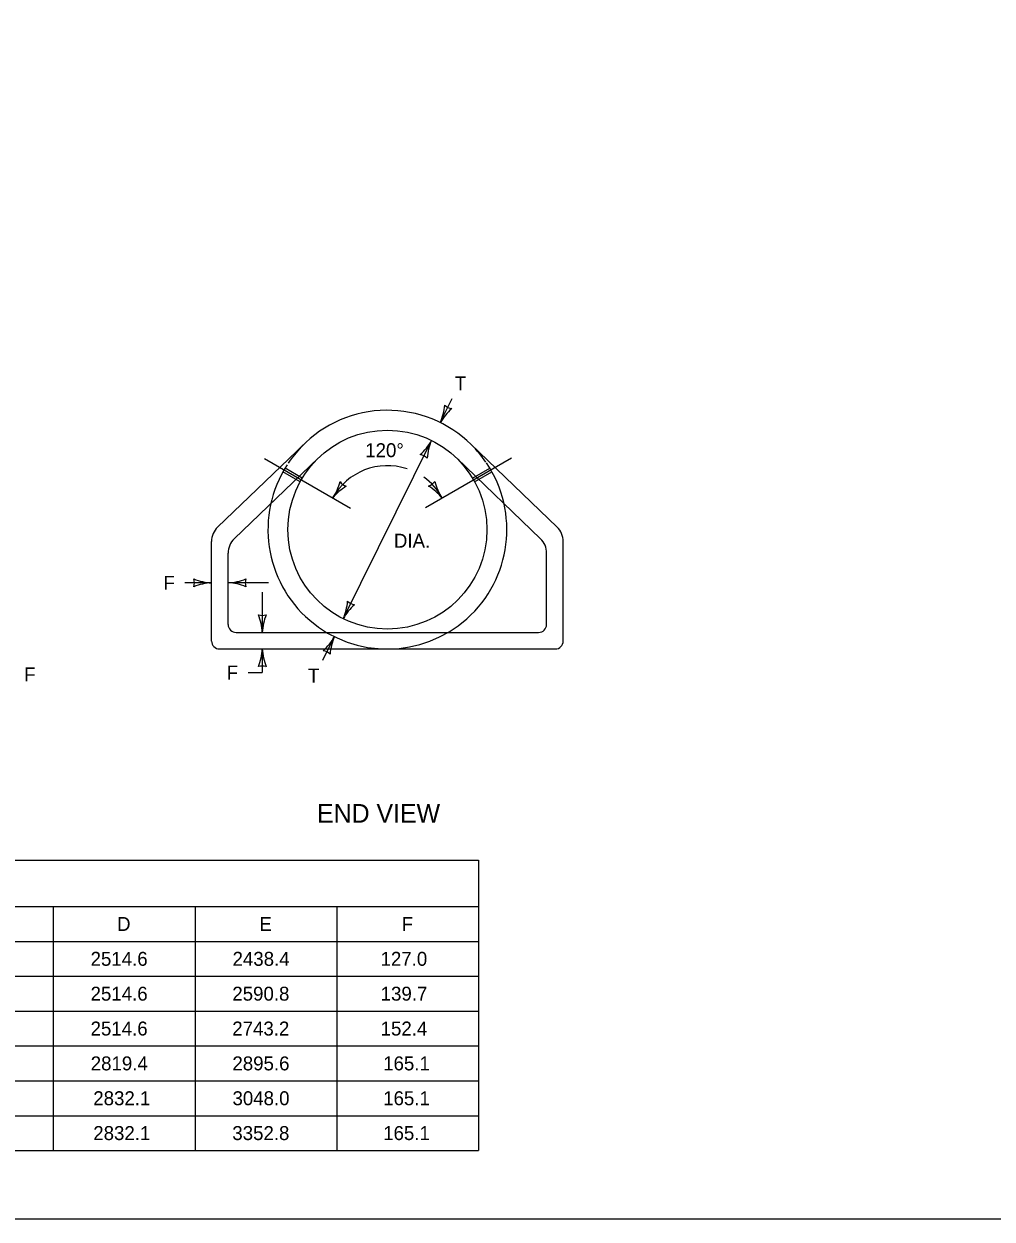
# Model space of a CAD drawing. Extents: x 49991.4 to 50022.1, y 49985 to 50011.4.
# Drawn here: x 50004.5 to 50008.67, y 49987.8 to 49992.94 of the extents above; entities that cross this region are included whole.
import ezdxf

# ---------------------------------------------------------------- set-up
doc = ezdxf.new("R2010")
doc.units = 0
for name, color, linetype in [('Level 1', 7, 'Continuous'), ('Level 2', 7, 'Continuous'), ('Level 3', 7, 'Continuous'), ('Level 4', 7, 'Continuous'), ('Level 5', 7, 'Continuous')]:
    doc.layers.add(name, color=color, linetype=linetype)

msp = doc.modelspace()

# ---------------------------------------------------------------- linework, layer by layer
at = {"layer": 'Level 1'}
for p, q in [((50005.7097, 49991.1365), (50005.3354, 49990.7771)), ((50006.4229, 49991.1349), (50006.7955, 49990.7771)), ((50005.769, 49991.0748), (50005.4069, 49990.727)), ((50006.3637, 49991.0731), (50006.724, 49990.727)), ((50005.3091, 49990.2865), (50005.3091, 49990.7154)), ((50006.8218, 49990.2865), (50006.8218, 49990.7154)), ((50005.3805, 49990.3579), (50005.3805, 49990.6653)), ((50006.7504, 49990.3579), (50006.7504, 49990.6653)), ((50005.4148, 49990.3237), (50006.7161, 49990.3237)), ((50005.3434, 49990.2523), (50006.7875, 49990.2523))]:
    msp.add_line(p, q, dxfattribs=at)
msp.add_lwpolyline([(49999.3835, 49998.9992), (50016.7501, 49998.9992), (50016.7501, 49987.7988), (49999.3835, 49987.7988)], close=True, dxfattribs=at)
msp.add_circle((50006.0655, 49990.766), 0.4281, dxfattribs=at)
for centre, radius, start, end in [((50006.0655, 49990.766), 0.5137, 45.3824, 135.9308), ((50005.3947, 49990.7154), 0.0856, 133.8358, 180), ((50006.7362, 49990.7154), 0.0856, 0, 46.1636), ((50005.4661, 49990.6653), 0.0856, 133.8272, 180), ((50006.6648, 49990.6653), 0.0856, 0, 46.1643), ((50005.4148, 49990.3579), 0.0342, 180, 270), ((50006.7161, 49990.3579), 0.0342, 270, 0), ((50005.3434, 49990.2865), 0.0342, 180, 270), ((50006.7875, 49990.2865), 0.0342, 270, 0)]:
    msp.add_arc(centre, radius, start, end, dxfattribs=at)
at = {"layer": 'Level 2'}
for p, q in [((50000.968, 49989.3439), (50006.458, 49989.3439)), ((50006.458, 49989.3439), (50006.458, 49988.0939)), ((50000.968, 49989.1439), (50006.458, 49989.1439)), ((50004.628, 49989.1439), (50004.628, 49988.0939)), ((50005.238, 49989.1439), (50005.238, 49988.0939)), ((50005.848, 49989.1439), (50005.848, 49988.0939)), ((50000.968, 49988.9939), (50006.458, 49988.9939)), ((50000.968, 49988.8439), (50006.458, 49988.8439)), ((50000.968, 49988.6939), (50006.458, 49988.6939)), ((50000.968, 49988.5439), (50006.458, 49988.5439)), ((50000.968, 49988.3939), (50006.458, 49988.3939)), ((50000.968, 49988.2439), (50006.458, 49988.2439)), ((50000.968, 49988.0939), (50006.458, 49988.0939))]:
    msp.add_line(p, q, dxfattribs=at)
at = {"layer": 'Level 3'}
for p, q in [((50006.2932, 49991.2264), (50006.3444, 49991.33)), ((50005.8756, 49990.3823), (50006.2552, 49991.1497)), ((50005.3091, 49990.5371), (50005.1948, 49990.5371)), ((50005.5539, 49990.5371), (50005.3805, 49990.5371)), ((50005.5275, 49990.4971), (50005.5275, 49990.3237)), ((50005.7874, 49990.2039), (50005.8377, 49990.3055)), ((50005.5275, 49990.2523), (50005.5275, 49990.1509)), ((50005.4668, 49990.1509), (50005.5275, 49990.1509))]:
    msp.add_line(p, q, dxfattribs=at)
for centre, radius, start, end in [((50006.0795, 49991.3192), 0.233, 336.5283, 355.7782), ((50006.4883, 49991.1198), 0.2223, 131.157, 151.3405), ((50006.35, 49991.3414), 0.0548, 225.8398, 261.5622), ((50006.0602, 49991.2564), 0.2223, 311.1364, 331.3199), ((50006.4689, 49991.0568), 0.233, 156.5077, 175.7575), ((50006.1984, 49991.0348), 0.0548, 45.8192, 81.5415), ((50006.0649, 49990.7739), 0.2674, 71.4211, 151.4104), ((50005.6361, 49991.031), 0.233, 326.3378, 345.5877), ((50006.0032, 49990.7624), 0.2223, 120.9665, 141.15), ((50005.9063, 49991.0049), 0.0548, 215.6493, 251.3717), ((50006.0797, 49990.7873), 0.249, 27.393, 55.2173), ((50006.2252, 49991.0055), 0.0548, 288.2824, 324.0048), ((50006.1197, 49990.7554), 0.233, 38.9709, 58.2208), ((50006.4856, 49991.0255), 0.2223, 193.5996, 213.7831), ((50005.3183, 49990.7592), 0.2223, 247.456, 267.6395), ((50005.1809, 49990.5371), 0.0548, 342.1388, 17.8612), ((50005.369, 49990.7698), 0.233, 272.8273, 292.0772), ((50005.5087, 49990.5371), 0.0548, 162.1388, 197.8612), ((50005.3206, 49990.3044), 0.233, 92.8273, 112.0772), ((50005.3713, 49990.315), 0.2223, 67.456, 87.6395), ((50005.6619, 49990.4752), 0.233, 336.5077, 355.7575), ((50006.0706, 49990.2756), 0.2223, 131.1364, 151.3199), ((50005.9324, 49990.4972), 0.0548, 225.8192, 261.5415), ((50005.5275, 49990.4519), 0.0548, 252.1388, 287.8612), ((50005.2948, 49990.3122), 0.233, 2.8273, 22.0772), ((50005.7496, 49990.3145), 0.2223, 157.456, 177.6395), ((50005.6427, 49990.4123), 0.2223, 311.117, 331.3005), ((50006.0514, 49990.2126), 0.233, 156.4883, 175.7381), ((50005.3054, 49990.2615), 0.2223, 337.456, 357.6395), ((50005.7602, 49990.2638), 0.233, 182.8273, 202.0772), ((50005.7808, 49990.1906), 0.0548, 45.7998, 81.5221), ((50005.5275, 49990.1241), 0.0548, 72.1388, 107.8612)]:
    msp.add_arc(centre, radius, start, end, dxfattribs=at)
at = {"layer": 'Level 4'}
for p, q in [((50005.6907, 49990.9721), (50005.6161, 49991.015)), ((50005.6987, 49990.988), (50005.6251, 49991.0305)), ((50006.432, 49990.9879), (50006.5061, 49991.0307)), ((50006.4408, 49990.9724), (50006.5148, 49991.0151))]:
    msp.add_line(p, q, dxfattribs=at)
for start, end in [(136.134, 146.1916), (34.4729, 45.2134), (147.1466, 33.9701)]:
    msp.add_arc((50006.0655, 49990.766), 0.5137, start, end, dxfattribs=at)
at = {"layer": 'Level 5'}
for p, q in [((50005.5362, 49991.0717), (50005.9061, 49990.8579)), ((50006.5988, 49991.074), (50006.2289, 49990.8604))]:
    msp.add_line(p, q, dxfattribs=at)

# ---------------------------------------------------------------- texts
at = {"layer": 'Level 2'}
for s, height, p in [('T', 0.06, (50006.3557, 49991.3659)), ('120°', 0.06, (50005.9702, 49991.0778)), ('DIA.', 0.06, (50006.0936, 49990.6883)), ('F', 0.06, (50005.1024, 49990.5071)), ('F', 0.06, (50005.3744, 49990.1209)), ('F', 0.06, (50004.5032, 49990.1127)), ('T', 0.06, (50005.724, 49990.1081)), ('END VIEW', 0.08, (50005.7631, 49989.505)), ('D', 0.06, (50004.9027, 49989.0389)), ('E', 0.06, (50005.5151, 49989.0389)), ('F', 0.06, (50006.1269, 49989.0389)), ('2514.6', 0.06, (50004.7889, 49988.8889)), ('2438.4', 0.06, (50005.3995, 49988.8889)), ('127.0', 0.06, (50006.0361, 49988.8889)), ('2514.6', 0.06, (50004.7889, 49988.7389)), ('2590.8', 0.06, (50005.3985, 49988.7389)), ('139.7', 0.06, (50006.0366, 49988.7389)), ('2514.6', 0.06, (50004.7889, 49988.5889)), ('2743.2', 0.06, (50005.3983, 49988.5889)), ('152.4', 0.06, (50006.0364, 49988.5889)), ('2819.4', 0.06, (50004.7895, 49988.4389)), ('2895.6', 0.06, (50005.3989, 49988.4389)), ('165.1', 0.06, (50006.0474, 49988.4389)), ('2832.1', 0.06, (50004.8004, 49988.2889)), ('3048.0', 0.06, (50005.3992, 49988.2889)), ('165.1', 0.06, (50006.0474, 49988.2889)), ('2832.1', 0.06, (50004.8004, 49988.1389)), ('3352.8', 0.06, (50005.3985, 49988.1389)), ('165.1', 0.06, (50006.0474, 49988.1389))]:
    msp.add_text(s, height=height, dxfattribs=at).set_placement(p)

doc.saveas('drawing.dxf')
